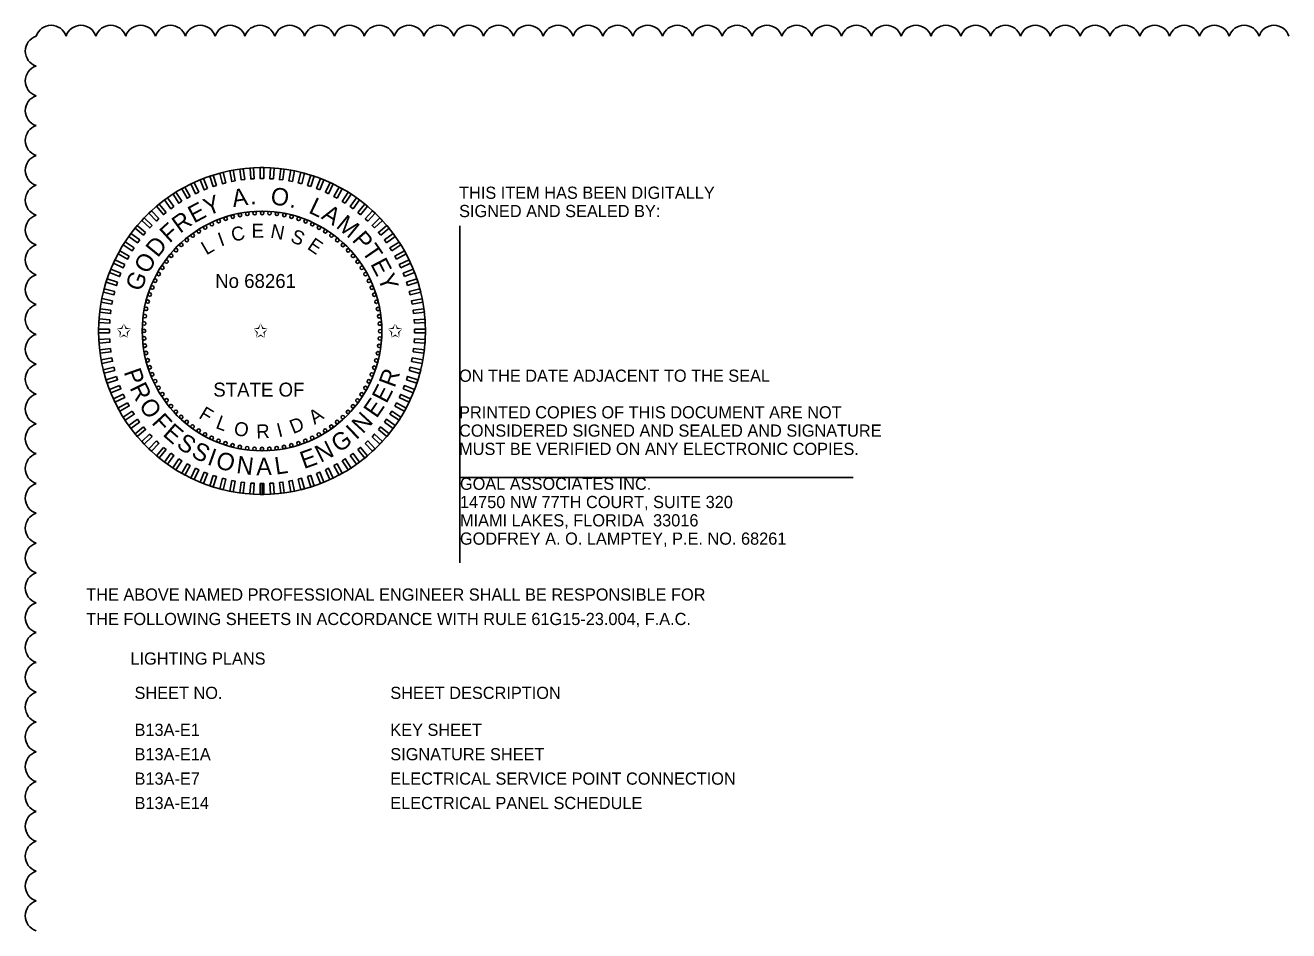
# Model space of a CAD drawing. Extents: x -811.3 to -795.2, y -2199.5 to -2188.9.
# Drawn here: x -810.85 to -803.6, y -2194.13 to -2188.94 of the extents above; entities that cross this region are included whole.
import ezdxf

# ---------------------------------------------------------------- set-up
doc = ezdxf.new("R2010")
doc.units = 0
for name, color, linetype in [('PlotBorder_dp', 7, 'Continuous'), ('ScratchEle_dp', 7, 'Continuous'), ('SheetBorder_dp', 7, 'Continuous'), ('SheetLines_dp', 7, 'Continuous'), ('TextMinor', 7, 'Continuous'), ('TextMisc', 7, 'Continuous')]:
    doc.layers.add(name, color=color, linetype=linetype)

msp = doc.modelspace()

# ---------------------------------------------------------------- linework, layer by layer
at = {"layer": 'PlotBorder_dp'}
for p, q in [((-809.5001, -2191.6301), (-809.5003, -2191.5676)), ((-809.4901, -2191.6301), (-809.4903, -2191.5676)), ((-809.4801, -2191.6301), (-809.4803, -2191.5676))]:
    msp.add_line(p, q, dxfattribs=at)
for points in [[(-809.7508, -2189.8572), (-809.77, -2189.8635), (-809.7893, -2189.8041), (-809.7701, -2189.7979)], [(-809.6979, -2189.8425), (-809.7174, -2189.8475), (-809.7329, -2189.7871), (-809.7134, -2189.782)], [(-809.6441, -2189.8312), (-809.6639, -2189.8349), (-809.6756, -2189.7736), (-809.6558, -2189.7698)], [(-809.5897, -2189.8232), (-809.6097, -2189.8257), (-809.6175, -2189.7638), (-809.5975, -2189.7612)], [(-809.5349, -2189.8187), (-809.555, -2189.8199), (-809.559, -2189.7576), (-809.5388, -2189.7563)], [(-809.4799, -2189.8176), (-809.5001, -2189.8176), (-809.5001, -2189.7551), (-809.4799, -2189.7551)], [(-809.425, -2189.8199), (-809.4452, -2189.8187), (-809.4412, -2189.7563), (-809.4211, -2189.7576)], [(-809.3703, -2189.8257), (-809.3904, -2189.8232), (-809.3825, -2189.7613), (-809.3625, -2189.7638)], [(-809.3162, -2189.835), (-809.336, -2189.8312), (-809.3243, -2189.7699), (-809.3045, -2189.7736)], [(-809.2626, -2189.8476), (-809.2822, -2189.8426), (-809.2667, -2189.7821), (-809.2471, -2189.7871)], [(-809.21, -2189.8635), (-809.2292, -2189.8573), (-809.2099, -2189.7979), (-809.1907, -2189.8042)], [(-809.9027, -2189.9209), (-809.9204, -2189.9306), (-809.9505, -2189.8759), (-809.9328, -2189.8662)], [(-809.8535, -2189.8965), (-809.8717, -2189.9051), (-809.8983, -2189.8486), (-809.8801, -2189.84)], [(-809.8028, -2189.8753), (-809.8215, -2189.8827), (-809.8445, -2189.8246), (-809.8258, -2189.8172)], [(-809.1585, -2189.8828), (-809.1773, -2189.8753), (-809.1543, -2189.8173), (-809.1355, -2189.8247)], [(-809.1083, -2189.9052), (-809.1266, -2189.8966), (-809.1, -2189.8401), (-809.0817, -2189.8487)], [(-809.0596, -2189.9307), (-809.0773, -2189.921), (-809.0473, -2189.8663), (-809.0296, -2189.876)], [(-809.9962, -2189.9787), (-810.0125, -2189.9906), (-810.0492, -2189.94), (-810.0329, -2189.9282)], [(-809.9504, -2189.9483), (-809.9674, -2189.9591), (-810.0009, -2189.9064), (-809.9838, -2189.8956)], [(-809.0127, -2189.9592), (-809.0297, -2189.9484), (-808.9962, -2189.8957), (-808.9792, -2189.9065)], [(-808.9676, -2189.9907), (-808.9839, -2189.9788), (-808.9472, -2189.9283), (-808.9308, -2189.9402)], [(-810.0817, -2190.0478), (-810.0964, -2190.0616), (-810.1392, -2190.0161), (-810.1244, -2190.0022)], [(-810.04, -2190.0119), (-810.0556, -2190.0247), (-810.0954, -2189.9766), (-810.0798, -2189.9638)], [(-808.9245, -2190.0249), (-808.9401, -2190.012), (-808.9003, -2189.9639), (-808.8847, -2189.9768)], [(-808.8837, -2190.0617), (-808.8984, -2190.0479), (-808.8557, -2190.0024), (-808.841, -2190.0162)], [(-810.1579, -2190.127), (-810.1707, -2190.1425), (-810.2188, -2190.1027), (-810.206, -2190.0872)], [(-810.121, -2190.0862), (-810.1348, -2190.1009), (-810.1804, -2190.0581), (-810.1665, -2190.0434)], [(-808.8453, -2190.101), (-808.8591, -2190.0863), (-808.8136, -2190.0436), (-808.7998, -2190.0583)], [(-808.8094, -2190.1427), (-808.8223, -2190.1271), (-808.7742, -2190.0873), (-808.7613, -2190.1029)], [(-810.192, -2190.17), (-810.2039, -2190.1864), (-810.2544, -2190.1497), (-810.2426, -2190.1333)], [(-808.7762, -2190.1865), (-808.7881, -2190.1702), (-808.7376, -2190.1335), (-808.7257, -2190.1498)], [(-810.252, -2190.2621), (-810.2617, -2190.2798), (-810.3164, -2190.2497), (-810.3067, -2190.232)], [(-810.2235, -2190.2151), (-810.2343, -2190.2322), (-810.287, -2190.1987), (-810.2762, -2190.1817)], [(-808.7459, -2190.2323), (-808.7567, -2190.2153), (-808.7039, -2190.1818), (-808.6931, -2190.1989)], [(-808.7184, -2190.28), (-808.7281, -2190.2623), (-808.6734, -2190.2322), (-808.6637, -2190.2499)], [(-810.2775, -2190.3108), (-810.2861, -2190.3291), (-810.3426, -2190.3025), (-810.334, -2190.2842)], [(-808.694, -2190.3292), (-808.7026, -2190.311), (-808.6461, -2190.2844), (-808.6375, -2190.3027)], [(-810.3, -2190.361), (-810.3074, -2190.3798), (-810.3654, -2190.3568), (-810.358, -2190.338)], [(-808.6728, -2190.3799), (-808.6802, -2190.3612), (-808.6222, -2190.3382), (-808.6147, -2190.357)], [(-810.3351, -2190.4651), (-810.3401, -2190.4847), (-810.4006, -2190.4691), (-810.3956, -2190.4496)], [(-810.3192, -2190.4125), (-810.3254, -2190.4317), (-810.3848, -2190.4124), (-810.3786, -2190.3932)], [(-808.6548, -2190.4319), (-808.661, -2190.4127), (-808.6016, -2190.3934), (-808.5954, -2190.4126)], [(-808.64, -2190.4849), (-808.6451, -2190.4653), (-808.5846, -2190.4498), (-808.5796, -2190.4693)], [(-810.3477, -2190.5186), (-810.3515, -2190.5385), (-810.4129, -2190.5268), (-810.4091, -2190.5069)], [(-808.6287, -2190.5386), (-808.6325, -2190.5188), (-808.5711, -2190.5071), (-808.5673, -2190.5269)], [(-810.357, -2190.5728), (-810.3595, -2190.5928), (-810.4215, -2190.585), (-810.4189, -2190.565)], [(-808.6207, -2190.593), (-808.6232, -2190.573), (-808.5613, -2190.5652), (-808.5588, -2190.5852)], [(-810.3628, -2190.6275), (-810.3641, -2190.6476), (-810.4264, -2190.6437), (-810.4251, -2190.6236)], [(-808.6162, -2190.6478), (-808.6174, -2190.6277), (-808.5551, -2190.6238), (-808.5539, -2190.6439)], [(-810.3652, -2190.6824), (-810.3652, -2190.7026), (-810.4276, -2190.7026), (-810.4276, -2190.6824)], [(-810.3641, -2190.7374), (-810.3628, -2190.7575), (-810.4251, -2190.7614), (-810.4264, -2190.7413)], [(-808.6175, -2190.7577), (-808.6162, -2190.7376), (-808.5539, -2190.7415), (-808.5551, -2190.7616)], [(-808.6151, -2190.7028), (-808.6151, -2190.6826), (-808.5527, -2190.6826), (-808.5527, -2190.7028)], [(-810.3595, -2190.7922), (-810.357, -2190.8122), (-810.4189, -2190.82), (-810.4215, -2190.8)], [(-808.6233, -2190.8124), (-808.6207, -2190.7923), (-808.5588, -2190.8002), (-808.5613, -2190.8202)], [(-810.3516, -2190.8466), (-810.3478, -2190.8664), (-810.4091, -2190.8781), (-810.4129, -2190.8583)], [(-808.6325, -2190.8666), (-808.6287, -2190.8467), (-808.5674, -2190.8584), (-808.5712, -2190.8783)], [(-810.3402, -2190.9003), (-810.3352, -2190.9199), (-810.3957, -2190.9354), (-810.4007, -2190.9159)], [(-810.3255, -2190.9533), (-810.3192, -2190.9725), (-810.3786, -2190.9918), (-810.3849, -2190.9726)], [(-808.6611, -2190.9727), (-808.6548, -2190.9535), (-808.5954, -2190.9728), (-808.6017, -2190.992)], [(-808.6451, -2190.9201), (-808.6401, -2190.9005), (-808.5796, -2190.916), (-808.5846, -2190.9356)], [(-810.3075, -2191.0052), (-810.3, -2191.024), (-810.3581, -2191.047), (-810.3655, -2191.0282)], [(-808.6803, -2191.0242), (-808.6729, -2191.0054), (-808.6148, -2191.0284), (-808.6222, -2191.0472)], [(-810.2862, -2191.0559), (-810.2776, -2191.0742), (-810.3341, -2191.1008), (-810.3427, -2191.0825)], [(-810.2618, -2191.1052), (-810.2521, -2191.1229), (-810.3068, -2191.153), (-810.3165, -2191.1353)], [(-808.7282, -2191.1231), (-808.7185, -2191.1054), (-808.6638, -2191.1355), (-808.6735, -2191.1532)], [(-808.7027, -2191.0744), (-808.6941, -2191.0561), (-808.6376, -2191.0827), (-808.6462, -2191.101)], [(-810.2344, -2191.1529), (-810.2236, -2191.1699), (-810.2763, -2191.2034), (-810.2871, -2191.1863)], [(-808.7568, -2191.1701), (-808.746, -2191.153), (-808.6932, -2191.1865), (-808.704, -2191.2035)], [(-810.204, -2191.1987), (-810.1922, -2191.215), (-810.2427, -2191.2517), (-810.2545, -2191.2354)], [(-810.1708, -2191.2425), (-810.158, -2191.2581), (-810.2061, -2191.2979), (-810.2189, -2191.2823)], [(-808.8224, -2191.2582), (-808.8095, -2191.2427), (-808.7614, -2191.2825), (-808.7743, -2191.298)], [(-808.7882, -2191.2152), (-808.7763, -2191.1988), (-808.7258, -2191.2355), (-808.7377, -2191.2519)], [(-810.135, -2191.2842), (-810.1211, -2191.2989), (-810.1667, -2191.3416), (-810.1805, -2191.3269)], [(-810.0965, -2191.3235), (-810.0818, -2191.3373), (-810.1246, -2191.3828), (-810.1393, -2191.369)], [(-808.8985, -2191.3374), (-808.8838, -2191.3236), (-808.8411, -2191.3691), (-808.8558, -2191.383)], [(-808.8592, -2191.299), (-808.8454, -2191.2843), (-808.7999, -2191.327), (-808.8137, -2191.3418)], [(-810.0557, -2191.3603), (-810.0402, -2191.3732), (-810.08, -2191.4213), (-810.0955, -2191.4084)], [(-810.0127, -2191.3945), (-809.9964, -2191.4064), (-810.0331, -2191.4569), (-810.0494, -2191.445)], [(-808.984, -2191.4065), (-808.9677, -2191.3946), (-808.931, -2191.4451), (-808.9473, -2191.457)], [(-808.9402, -2191.3733), (-808.9247, -2191.3604), (-808.8848, -2191.4086), (-808.9004, -2191.4214)], [(-809.9676, -2191.426), (-809.9505, -2191.4368), (-809.984, -2191.4895), (-810.001, -2191.4787)], [(-809.9206, -2191.4545), (-809.9029, -2191.4642), (-809.933, -2191.5189), (-809.9507, -2191.5092)], [(-809.0775, -2191.4643), (-809.0598, -2191.4546), (-809.0297, -2191.5093), (-809.0474, -2191.519)], [(-809.0299, -2191.4369), (-809.0128, -2191.4261), (-808.9794, -2191.4788), (-808.9964, -2191.4896)], [(-809.8719, -2191.48), (-809.8536, -2191.4886), (-809.8802, -2191.5451), (-809.8985, -2191.5365)], [(-809.8217, -2191.5024), (-809.8029, -2191.5099), (-809.8259, -2191.5679), (-809.8447, -2191.5605)], [(-809.7702, -2191.5217), (-809.751, -2191.5279), (-809.7703, -2191.5873), (-809.7895, -2191.581)], [(-809.7176, -2191.5376), (-809.698, -2191.5426), (-809.7136, -2191.6031), (-809.7331, -2191.5981)], [(-809.2824, -2191.5427), (-809.2628, -2191.5376), (-809.2473, -2191.5981), (-809.2668, -2191.6031)], [(-809.2294, -2191.5279), (-809.2102, -2191.5217), (-809.1909, -2191.5811), (-809.2101, -2191.5873)], [(-809.1775, -2191.5099), (-809.1587, -2191.5025), (-809.1357, -2191.5606), (-809.1545, -2191.568)], [(-809.1268, -2191.4887), (-809.1085, -2191.4801), (-809.0819, -2191.5366), (-809.1002, -2191.5452)], [(-809.6641, -2191.5502), (-809.6443, -2191.554), (-809.656, -2191.6153), (-809.6758, -2191.6116)], [(-809.6099, -2191.5594), (-809.5899, -2191.562), (-809.5977, -2191.6239), (-809.6177, -2191.6214)], [(-809.5552, -2191.5653), (-809.5351, -2191.5665), (-809.539, -2191.6288), (-809.5592, -2191.6276)], [(-809.5003, -2191.5676), (-809.4801, -2191.5676), (-809.4801, -2191.6301), (-809.5003, -2191.6301)], [(-809.4453, -2191.5665), (-809.4252, -2191.5653), (-809.4213, -2191.6276), (-809.4414, -2191.6289)], [(-809.3906, -2191.562), (-809.3705, -2191.5595), (-809.3627, -2191.6214), (-809.3827, -2191.624)], [(-809.3362, -2191.554), (-809.3163, -2191.5503), (-809.3046, -2191.6116), (-809.3245, -2191.6154)]]:
    msp.add_lwpolyline(points, close=True, dxfattribs=at)
for centre in [(-809.6165, -2190.027), (-809.5745, -2190.0204), (-809.5321, -2190.0164), (-809.4896, -2190.0151), (-809.447, -2190.0165), (-809.4047, -2190.0205), (-809.3626, -2190.0272), (-809.816, -2190.0987), (-809.7781, -2190.0794), (-809.739, -2190.0625), (-809.6989, -2190.0481), (-809.6581, -2190.0363), (-809.3211, -2190.0366), (-809.2802, -2190.0485), (-809.2402, -2190.0629), (-809.2012, -2190.0798), (-809.1633, -2190.0992), (-809.9215, -2190.1702), (-809.8879, -2190.1442), (-809.8527, -2190.1203), (-809.1266, -2190.1209), (-809.0915, -2190.1448), (-809.0579, -2190.171), (-809.9836, -2190.2284), (-809.9535, -2190.1984), (-809.026, -2190.1991), (-808.9959, -2190.2292), (-810.0379, -2190.2939), (-810.0118, -2190.2603), (-808.9678, -2190.2612), (-808.9417, -2190.2948), (-810.0835, -2190.3657), (-810.0618, -2190.3291), (-808.9178, -2190.3301), (-808.8962, -2190.3667), (-810.1198, -2190.4427), (-810.1029, -2190.4036), (-808.8769, -2190.4047), (-808.86, -2190.4437), (-810.1462, -2190.5236), (-810.1343, -2190.4827), (-808.8456, -2190.4838), (-808.8338, -2190.5247), (-810.1622, -2190.6071), (-810.1555, -2190.5651), (-808.8245, -2190.5662), (-808.8179, -2190.6082), (-810.1662, -2190.6495), (-808.814, -2190.6506), (-810.1676, -2190.692), (-810.1663, -2190.7346), (-808.814, -2190.7357), (-808.8127, -2190.6932), (-810.1623, -2190.7769), (-810.1557, -2190.819), (-808.8248, -2190.8201), (-808.8181, -2190.7781), (-810.1464, -2190.8605), (-810.1346, -2190.9014), (-808.846, -2190.9025), (-808.8341, -2190.8616), (-810.1202, -2190.9415), (-808.8604, -2190.9425), (-810.1034, -2190.9805), (-810.0841, -2191.0185), (-808.8967, -2191.0195), (-808.8774, -2190.9816), (-810.0624, -2191.0551), (-810.0385, -2191.0903), (-808.9424, -2191.0913), (-808.9184, -2191.0561), (-810.0125, -2191.124), (-809.9844, -2191.1559), (-809.9543, -2191.1861), (-809.0268, -2191.1868), (-808.9967, -2191.1568), (-808.9685, -2191.1249), (-809.9224, -2191.2142), (-809.8888, -2191.2403), (-809.8536, -2191.2643), (-809.1276, -2191.2649), (-809.0924, -2191.241), (-809.0587, -2191.215), (-809.817, -2191.286), (-809.7791, -2191.3053), (-809.74, -2191.3223), (-809.7, -2191.3367), (-809.2813, -2191.3371), (-809.2413, -2191.3227), (-809.2022, -2191.3058), (-809.1642, -2191.2865), (-809.6591, -2191.3486), (-809.6176, -2191.358), (-809.5756, -2191.3647), (-809.5332, -2191.3687), (-809.4901, -2191.3701), (-809.4481, -2191.3688), (-809.4058, -2191.3648), (-809.3637, -2191.3582), (-809.3222, -2191.3489)]:
    msp.add_circle(centre, 0.01, dxfattribs=at)
at = {"layer": 'ScratchEle_dp'}
for centre, start, end in [((-810.7588, -2189.0862), 107.5, 252.5), ((-810.7002, -2189.0276), 17.5, 162.5), ((-810.5291, -2189.0276), 17.5, 162.5), ((-810.358, -2189.0276), 17.5, 162.5), ((-810.1868, -2189.0276), 17.5, 162.5), ((-810.0157, -2189.0276), 17.5, 162.5), ((-809.8446, -2189.0276), 17.5, 162.5), ((-809.6735, -2189.0276), 17.5, 162.5), ((-809.5024, -2189.0276), 17.5, 162.5), ((-809.3312, -2189.0276), 17.5, 162.5), ((-809.1601, -2189.0276), 17.5, 162.5), ((-808.989, -2189.0276), 17.5, 162.5), ((-808.8179, -2189.0276), 17.5, 162.5), ((-808.6467, -2189.0276), 17.5, 162.5), ((-808.4756, -2189.0276), 17.5, 162.5), ((-808.3045, -2189.0276), 17.5, 162.5), ((-808.1334, -2189.0276), 17.5, 162.5), ((-807.9622, -2189.0276), 17.5, 162.5), ((-807.7911, -2189.0276), 17.5, 162.5), ((-807.62, -2189.0276), 17.5, 162.5), ((-807.4489, -2189.0276), 17.5, 162.5), ((-807.2778, -2189.0276), 17.5, 162.5), ((-807.1066, -2189.0276), 17.5, 162.5), ((-806.9355, -2189.0276), 17.5, 162.5), ((-806.7644, -2189.0276), 17.5, 162.5), ((-806.5933, -2189.0276), 17.5, 162.5), ((-806.4221, -2189.0276), 17.5, 162.5), ((-806.251, -2189.0276), 17.5, 162.5), ((-806.0799, -2189.0276), 17.5, 162.5), ((-805.9088, -2189.0276), 17.5, 162.5), ((-805.7377, -2189.0276), 17.5, 162.5), ((-805.5665, -2189.0276), 17.5, 162.5), ((-805.3954, -2189.0276), 17.5, 162.5), ((-805.2243, -2189.0276), 17.5, 162.5), ((-805.0532, -2189.0276), 17.5, 162.5), ((-804.882, -2189.0276), 17.5, 162.5), ((-804.7109, -2189.0276), 17.5, 162.5), ((-804.5398, -2189.0276), 17.5, 162.5), ((-804.3687, -2189.0276), 17.5, 162.5), ((-804.1976, -2189.0276), 17.5, 162.5), ((-804.0264, -2189.0276), 17.5, 162.5), ((-803.8553, -2189.0276), 17.5, 162.5), ((-803.6842, -2189.0276), 17.5, 162.5), ((-810.7588, -2189.2573), 107.5, 252.5), ((-810.7588, -2189.4284), 107.5, 252.5), ((-810.7588, -2189.5996), 107.5, 252.5), ((-810.7588, -2189.7707), 107.5, 252.5), ((-810.7588, -2189.9418), 107.5, 252.5), ((-810.7588, -2190.1129), 107.5, 252.5), ((-810.7588, -2190.2841), 107.5, 252.5), ((-810.7588, -2190.4552), 107.5, 252.5), ((-810.7588, -2190.6263), 107.5, 252.5), ((-810.7588, -2190.7974), 107.5, 252.5), ((-810.7588, -2190.9685), 107.5, 252.5), ((-810.7588, -2191.1397), 107.5, 252.5), ((-810.7588, -2191.3108), 107.5, 252.5), ((-810.7588, -2191.4819), 107.5, 252.5), ((-810.7588, -2191.653), 107.5, 252.5), ((-810.7588, -2191.8242), 107.5, 252.5), ((-810.7588, -2191.9953), 107.5, 252.5), ((-810.7588, -2192.1664), 107.5, 252.5), ((-810.7588, -2192.3375), 107.5, 252.5), ((-810.7588, -2192.5087), 107.5, 252.5), ((-810.7588, -2192.6798), 107.5, 252.5), ((-810.7588, -2192.8509), 107.5, 252.5), ((-810.7588, -2193.022), 107.5, 252.5), ((-810.7588, -2193.1931), 107.5, 252.5), ((-810.7588, -2193.3643), 107.5, 252.5), ((-810.7588, -2193.5354), 107.5, 252.5), ((-810.7588, -2193.7065), 107.5, 252.5), ((-810.7588, -2193.8776), 107.5, 252.5), ((-810.7588, -2194.0488), 107.5, 252.5)]:
    msp.add_arc(centre, 0.0897, start, end, dxfattribs=at)
at = {"layer": 'SheetLines_dp'}
for radius in [0.9375, 0.6875]:
    msp.add_circle((-809.4901, -2190.6926), radius, dxfattribs=at)
at = {"layer": 'TextMisc'}
for p, q in [((-808.3546, -2190.0892), (-808.3546, -2192.0239)), ((-808.3546, -2191.5339), (-806.0979, -2191.5339))]:
    msp.add_line(p, q, dxfattribs=at)

# ---------------------------------------------------------------- texts
at = {"layer": 'PlotBorder_dp'}
for s, height, rotation, p in [('A', 0.1, 8.80884, (-809.6551, -2189.982)), ('O', 0.1, 352.18771, (-809.4449, -2189.9645)), ('E', 0.1, 28.10553, (-809.8806, -2190.0764)), ('Y', 0.1, 21.06329, (-809.8021, -2190.0332)), ('.', 0.1, 1.04184, (-809.5575, -2189.9662)), ('L', 0.1, 334.67271, (-809.2279, -2190.0118)), ('R', 0.1, 35.92688, (-809.9609, -2190.1353)), ('.', 0.1, 343.52684, (-809.3358, -2189.9796)), ('A', 0.1, 328.40959, (-809.1552, -2190.0445)), ('F', 0.1, 42.37723, (-810.0205, -2190.1917)), ('C', 0.08, 12.20255, (-809.6579, -2190.181)), ('E', 0.08, 0.41861, (-809.5498, -2190.1575)), ('N', 0.08, 349.29143, (-809.4455, -2190.1561)), ('M', 0.1, 320.6426, (-809.0707, -2190.0957)), ('D', 0.1, 50.8569, (-810.0886, -2190.2754)), ('I', 0.08, 20.01168, (-809.7258, -2190.2085)), ('S', 0.08, 337.02207, (-809.3325, -2190.1778)), ('E', 0.08, 325.86633, (-809.2358, -2190.218)), ('P', 0.1, 311.19658, (-808.9784, -2190.1727)), ('L', 0.08, 30.40215, (-809.8093, -2190.259)), ('T', 0.1, 304.45632, (-808.9209, -2190.2363)), ('O', 0.1, 59.51777, (-810.1446, -2190.3702)), ('E', 0.1, 297.63152, (-808.8707, -2190.3072)), ('G', 0.1, 68.0518, (-810.1851, -2190.4709)), ('Y', 0.1, 290.58928, (-808.8281, -2190.386)), ('P', 0.1, 289.40551, (-810.2848, -2190.9272)), ('R', 0.1, 69.5134, (-808.7299, -2191.0223)), ('R', 0.1, 296.14576, (-810.2518, -2191.0188)), ('E', 0.1, 62.47116, (-808.7761, -2191.113)), ('O', 0.1, 303.96711, (-810.2003, -2191.1194)), ('E', 0.1, 55.42892, (-808.833, -2191.1974)), ('F', 0.1, 312.62798, (-810.1279, -2191.2215)), ('F', 0.08, 328.72408, (-809.8582, -2191.1892)), ('L', 0.08, 339.29159, (-809.7609, -2191.2483)), ('A', 0.08, 34.49917, (-809.1883, -2191.232)), ('N', 0.1, 47.17876, (-808.9123, -2191.2864)), ('E', 0.1, 319.07833, (-810.0645, -2191.2898)), ('O', 0.08, 349.68206, (-809.6562, -2191.288)), ('R', 0.08, 2.33977, (-809.5217, -2191.3099)), ('I', 0.08, 14.20366, (-809.3941, -2191.3032)), ('D', 0.08, 22.01279, (-809.312, -2191.2845)), ('I', 0.1, 43.64556, (-808.9499, -2191.3209)), ('S', 0.1, 326.12056, (-809.9869, -2191.3557)), ('N', 0.1, 26.86136, (-809.1544, -2191.4501)), ('G', 0.1, 35.11153, (-809.0492, -2191.3941)), ('S', 0.1, 333.193, (-809.9015, -2191.4119)), ('I', 0.1, 340.26543, (-809.8098, -2191.457)), ('O', 0.1, 343.79863, (-809.7621, -2191.4753)), ('E', 0.1, 19.81912, (-809.2498, -2191.4856)), ('N', 0.1, 352.45949, (-809.6411, -2191.5073)), ('A', 0.1, 0.70966, (-809.5227, -2191.5206)), ('L', 0.1, 8.47665, (-809.4105, -2191.5174))]:
    msp.add_text(s, height=height, rotation=rotation, dxfattribs=at).set_placement(p)
for s, p in [('No 68261', (-809.7591, -2190.4454)), ('✩', (-810.3251, -2190.7305)), ('✩', (-809.5404, -2190.7305)), ('✩', (-808.7685, -2190.7305)), ('STATE OF', (-809.7698, -2191.0688))]:
    msp.add_text(s, height=0.08, dxfattribs=at).set_placement(p)
at = {"layer": 'SheetBorder_dp'}
for s, p in [('THIS ITEM HAS BEEN DIGITALLY', (-808.3596, -2189.934)), ('SIGNED AND SEALED BY:', (-808.3596, -2190.039)), ('ON THE DATE ADJACENT TO THE SEAL', (-808.3596, -2190.984)), ('PRINTED COPIES OF THIS DOCUMENT ARE NOT ', (-808.3596, -2191.194)), ('CONSIDERED SIGNED AND SEALED AND SIGNATURE ', (-808.3596, -2191.299)), ('MUST BE VERIFIED ON ANY ELECTRONIC COPIES.', (-808.3596, -2191.404)), ('GOAL ASSOCIATES INC.', (-808.3546, -2191.6039)), ('14750 NW 77TH COURT, SUITE 320', (-808.3546, -2191.7089)), ('MIAMI LAKES, FLORIDA  33016', (-808.3546, -2191.8139)), ('GODFREY A. O. LAMPTEY, P.E. NO. 68261', (-808.3546, -2191.9189)), ('THE ABOVE NAMED PROFESSIONAL ENGINEER SHALL BE RESPONSIBLE FOR ', (-810.4987, -2192.24)), ('THE FOLLOWING SHEETS IN ACCORDANCE WITH RULE 61G15-23.004, F.A.C.', (-810.4987, -2192.38)), ('LIGHTING PLANS', (-810.245, -2192.6071))]:
    msp.add_text(s, height=0.07, dxfattribs=at).set_placement(p)
at = {"layer": 'TextMinor'}
for s, p in [('SHEET NO.', (-810.2215, -2192.8041)), ('SHEET DESCRIPTION', (-808.7542, -2192.8041)), ('B13A-E1', (-810.2215, -2193.0162)), ('KEY SHEET', (-808.7542, -2193.0162)), ('B13A-E1A', (-810.2215, -2193.1562)), ('SIGNATURE SHEET', (-808.7542, -2193.1562)), ('B13A-E7', (-810.2215, -2193.2962)), ('ELECTRICAL SERVICE POINT CONNECTION', (-808.7542, -2193.2962)), ('B13A-E14', (-810.2215, -2193.4362)), ('ELECTRICAL PANEL SCHEDULE', (-808.7542, -2193.4362))]:
    msp.add_text(s, height=0.07, dxfattribs=at).set_placement(p)

doc.saveas('drawing.dxf')
